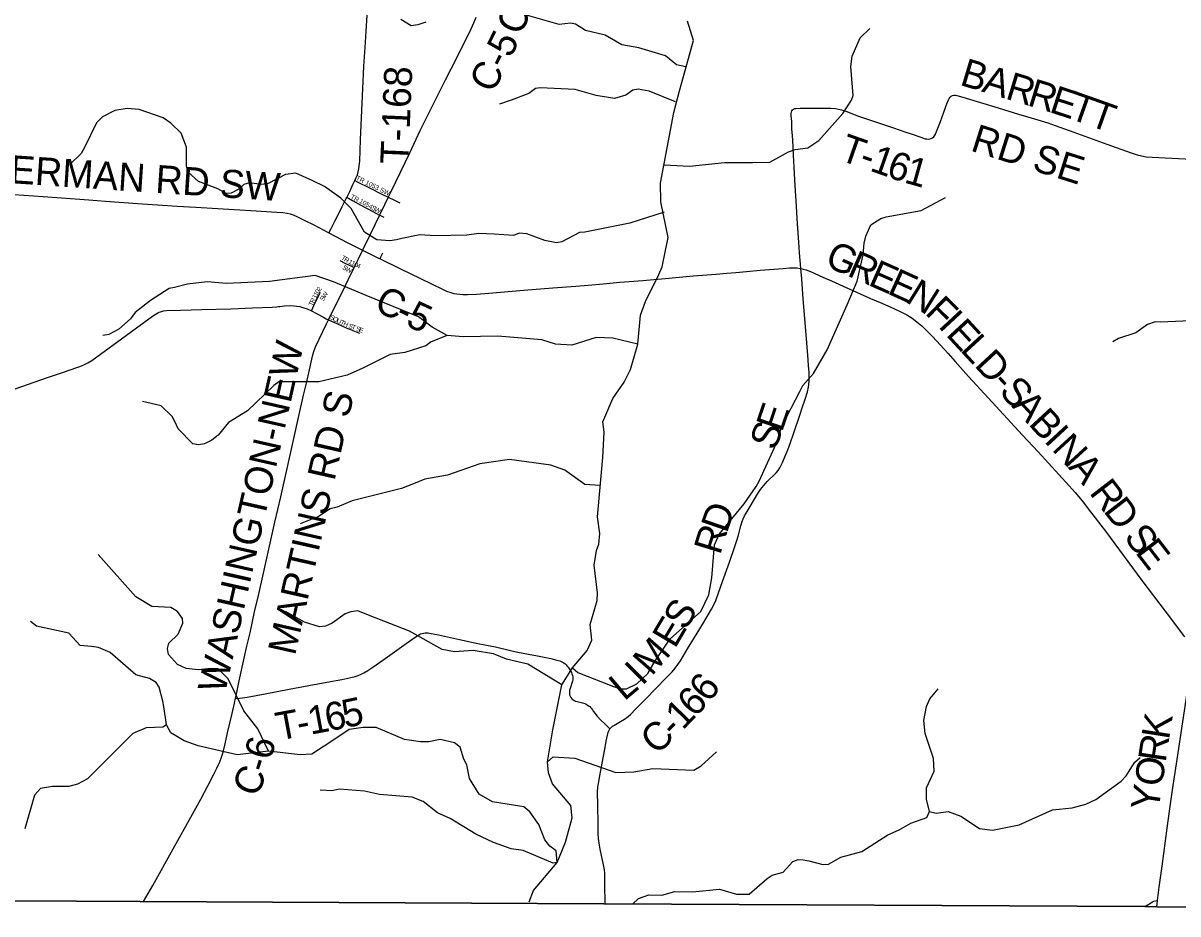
# Model space of a CAD drawing. Extents: x -51392 to 1635000, y 156707 to 696232.
# Drawn here: x 128219 to 140588, y 428826 to 438362 of the extents above; entities that cross this region are included whole.
import ezdxf

# ---------------------------------------------------------------- set-up
doc = ezdxf.new("R2010")
doc.units = 0
for name, color, linetype in [('GM_X_Adjacent_County', 7, 'Continuous'), ('GM_X_County', 7, 'Continuous'), ('GM_X_County_Road', 7, 'Continuous'), ('GM_X_County_Road_Text', 7, 'Continuous'), ('GM_X_Minor_River', 7, 'Continuous'), ('GM_X_Township', 7, 'Continuous'), ('GM_X_Township_Road', 7, 'Continuous'), ('GM_X_Township_Road_Text', 7, 'Continuous'), ('GM_X_Township_Subdivision', 7, 'Continuous'), ('GM_X_Township_Subdivision_Text', 7, 'Continuous')]:
    doc.layers.add(name, color=color, linetype=linetype)

msp = doc.modelspace()

# ---------------------------------------------------------------- linework, layer by layer
at = {"layer": 'GM_X_Adjacent_County'}
msp.add_lwpolyline([(104828, 429256), (108959, 429193), (114698, 429106), (118200, 429053), (121225, 429006), (121630, 429000), (123335, 428991), (129473, 428959), (134438, 428933), (140234, 428904), (140363, 428903), (142841, 428889), (147184, 428866), (150230, 428850), (152105, 428841), (155079, 428826)], dxfattribs=at)
at = {"layer": 'GM_X_County'}
msp.add_lwpolyline([(155079, 428826), (152105, 428841), (150230, 428850), (147184, 428866), (142841, 428889), (140363, 428903), (140234, 428904), (134438, 428933), (129473, 428959), (123335, 428991), (121630, 429000), (121225, 429006), (118200, 429053), (114698, 429106), (108959, 429193), (104828, 429256)], dxfattribs=at)
at = {"layer": 'GM_X_County_Road'}
for points in [[(133068, 438422), (133042, 438360), (133001, 438266), (132799, 437868), (132741, 437751), (132586, 437443), (132469, 437208), (132356, 436971), (132209, 436659), (132152, 436542), (132130, 436499)], [(136548, 435735), (136548, 435739), (136536, 435902), (136528, 436017), (136515, 436213), (136499, 436459), (136488, 436622), (136481, 436754), (136478, 436819), (136471, 436950), (136467, 437031), (136462, 437113), (136456, 437195), (136454, 437228), (136451, 437310), (136447, 437374), (136447, 437393), (136449, 437409), (136454, 437422), (136461, 437433)], [(132130, 436499), (132093, 436424), (132044, 436320), (132037, 436308)], [(132037, 436308), (131987, 436202), (131937, 436099), (131855, 435930)], [(131765, 435746), (131808, 435833), (131851, 435922), (131855, 435930)], [(131855, 435930), (132018, 435851), (132043, 435838)], [(131491, 435186), (131563, 435333), (131628, 435466), (131671, 435554), (131699, 435613), (131765, 435746)], [(132043, 435838), (132253, 435734), (132474, 435627), (132710, 435513), (132755, 435494), (132802, 435478), (132833, 435469), (132865, 435463), (132897, 435459), (132929, 435456), (132978, 435456), (133076, 435462), (133207, 435472), (133583, 435502), (133894, 435527), (134139, 435547), (134270, 435558), (134433, 435573), (134612, 435588), (134710, 435596), (134858, 435608), (135135, 435632), (135396, 435656), (135641, 435675), (135756, 435684), (135854, 435693), (135968, 435704), (136115, 435718), (136360, 435737), (136426, 435741), (136475, 435742), (136508, 435741), (136541, 435737), (136548, 435735)], [(134505, 430808), (134509, 430813), (134520, 430825), (134533, 430835), (134547, 430844), (134618, 430885), (134660, 430911), (134699, 430941), (134724, 430962), (134782, 431020), (134896, 431137), (134988, 431231), (135115, 431359), (135172, 431419), (135204, 431456), (135233, 431496), (135259, 431537), (135336, 431663), (135438, 431832), (135507, 431943), (135558, 432027), (135594, 432088), (135619, 432136), (135638, 432181), (135668, 432264), (135711, 432385), (135784, 432593), (135843, 432761), (135864, 432823), (135877, 432869), (135907, 432979), (135921, 433026), (135933, 433057), (135947, 433087), (135962, 433115), (136005, 433186), (136090, 433328), (136117, 433371), (136152, 433414), (136189, 433454), (136214, 433479), (136250, 433513), (136284, 433548), (136305, 433573), (136323, 433600), (136339, 433629), (136353, 433658), (136379, 433719), (136409, 433795), (136439, 433871), (136472, 433964), (136537, 434167), (136563, 434245), (136594, 434338), (136619, 434416), (136631, 434464), (136636, 434496), (136639, 434529), (136640, 434562), (136637, 434627), (136632, 434693), (136628, 434758), (136612, 434938), (136591, 435199), (136573, 435412), (136558, 435625), (136548, 435735)], [(136548, 435735), (136574, 435730), (136605, 435720), (136651, 435702), (136786, 435641), (136876, 435602), (137041, 435529), (137146, 435482), (137296, 435416), (137416, 435364), (137552, 435305), (137626, 435269), (137684, 435238), (137740, 435203), (137793, 435165), (137844, 435122), (137892, 435077), (137960, 435006), (138126, 434824), (138203, 434739), (138346, 434581), (138557, 434351), (138923, 433953), (139090, 433772), (139201, 433651), (139423, 433410), (139488, 433336), (139561, 433247), (139653, 433131), (139811, 432922), (140203, 432396), (140450, 432068), (140657, 431792)], [(130493, 431133), (130507, 431195), (130535, 431323), (130588, 431563), (130617, 431691), (130650, 431835), (130699, 432060), (130739, 432235), (130786, 432443), (130844, 432699), (130916, 433020), (130978, 433292), (131047, 433596), (131097, 433820), (131148, 434044), (131170, 434140), (131224, 434379), (131253, 434507), (131279, 434619), (131310, 434764), (131322, 434811), (131338, 434858), (131356, 434904), (131390, 434979), (131469, 435142), (131491, 435186)], [(140370, 428969), (140388, 429111), (140418, 429339), (140473, 429745), (140517, 430054), (140538, 430200), (140581, 430479), (140639, 430882), (140687, 431190), (140736, 431547), (140754, 431663)], [(129508, 428960), (129607, 429132), (129825, 429524), (129961, 429767), (130121, 430054), (130199, 430198), (130259, 430315), (130295, 430388), (130326, 430453), (130345, 430504), (130362, 430557), (130385, 430646), (130410, 430763), (130457, 430971), (130482, 431083), (130493, 431133)], [(134453, 428934), (134448, 429148), (134449, 429196), (134448, 429261), (134445, 429297), (134435, 429352), (134400, 429519), (134389, 429584), (134382, 429632), (134380, 429684), (134379, 429786), (134375, 429993), (134372, 430126), (134376, 430185), (134382, 430222), (134396, 430303), (134414, 430400), (134433, 430497), (134453, 430609), (134465, 430674), (134478, 430738), (134486, 430770), (134492, 430785), (134499, 430800), (134505, 430808)], [(140362, 428904), (140366, 428932), (140370, 428969)]]:
    msp.add_lwpolyline(points, dxfattribs=at)
at = {"layer": 'GM_X_Minor_River'}
for points in [[(132533, 438371), (132448, 438344), (132374, 438333), (132264, 438400)], [(135317, 437894), (135218, 437914), (135099, 438013), (134815, 438099), (134633, 438131), (134454, 438233), (134244, 438283), (134135, 438350), (134083, 438362), (133960, 438347), (133611, 438448)], [(133641, 428956), (133684, 429078), (133941, 429378), (134029, 429596), (134100, 429854), (134087, 429985), (133891, 430217), (133846, 430338), (133835, 430454), (133894, 430796), (133990, 431280), (134104, 431462), (134260, 431647), (134311, 431757), (134292, 431925), (134367, 432181), (134373, 432262), (134334, 432559), (134359, 432717), (134384, 432783), (134397, 432899), (134371, 433077), (134428, 433712), (134441, 433983), (134428, 434093), (134536, 434343), (134656, 434518), (134725, 434656), (134805, 434924), (134832, 435235), (134886, 435383), (135028, 435670), (135063, 435754), (135128, 436066), (135049, 436450), (135045, 436650), (135190, 437405), (135250, 437639), (135399, 438177), (135335, 438384)], [(135085, 436844), (135357, 436832), (135732, 436869), (136034, 436870), (136217, 436873), (136418, 436983), (136488, 437009), (136624, 437028), (136741, 437107), (136998, 437393), (137092, 437537), (137108, 437589), (137083, 437898), (137098, 438010), (137186, 438204), (137289, 438303)], [(135207, 437520), (134925, 437635), (134807, 437657), (134751, 437643), (134675, 437591), (134552, 437554), (134358, 437588), (134132, 437650), (133758, 437671), (133706, 437662), (133635, 437610), (133447, 437536), (133320, 437493)], [(135085, 436339), (134719, 436222), (134235, 436126), (134179, 436122), (133988, 436022), (133932, 436010), (133806, 436035), (133614, 436105), (133532, 436112), (133470, 436088), (133264, 436102), (133102, 436111), (132973, 436092), (132631, 436085), (132469, 436097), (132274, 436056), (132218, 436043), (132146, 436031), (132007, 436044), (131874, 436124), (131734, 436379), (131623, 436489), (131448, 436612), (131314, 436676), (131141, 436757), (131030, 436740), (130845, 436644), (130773, 436636), (130645, 436651), (130583, 436636), (130530, 436586), (130448, 436543), (130394, 436537), (130306, 436588), (130096, 436666), (129983, 436769), (129970, 436833), (129969, 437034), (129913, 437185), (129803, 437292), (129718, 437347), (129464, 437439), (129332, 437450), (129202, 437427), (129069, 437358), (129004, 437295), (128876, 437029), (128841, 436967), (128716, 436844)], [(134104, 431462), (134160, 431411), (134543, 431260), (134613, 431237), (134681, 431237), (134793, 431288), (134911, 431399), (134990, 431535), (135148, 431770), (135477, 432064), (135565, 432243), (135595, 432424), (135626, 432778), (135677, 432896), (135942, 433215), (136072, 433402), (136102, 433460), (136284, 433859), (136350, 434053), (136537, 434418), (136570, 434482), (136683, 434612), (136830, 434863), (137046, 435346), (137151, 435600), (137217, 435882), (137228, 436006), (137245, 436082), (137300, 436202), (137407, 436269), (137463, 436289), (137838, 436356), (138100, 436496)], [(134805, 434924), (134536, 434989), (134357, 434996), (134098, 434914), (133922, 434926), (133776, 434973), (133304, 435011), (132932, 435004), (132761, 435018), (132600, 435109), (132453, 435219), (131892, 435446), (131545, 435593), (131349, 435659), (130858, 435597), (130780, 435592), (130399, 435575), (130191, 435593), (129979, 435568), (129840, 435531), (129782, 435520), (129582, 435393), (129421, 435266), (129368, 435195), (129245, 435085), (129137, 435028), (129074, 435019)], [(140806, 435180), (140399, 435161), (140343, 435164), (140263, 435137), (140138, 435045), (139951, 434985), (139889, 434949)], [(132761, 435018), (132591, 434951), (132534, 434907), (132307, 434837), (132151, 434816), (131857, 434670), (131690, 434592), (131387, 434522), (130957, 434522), (130904, 434484), (130623, 434212), (130418, 434087), (130309, 433952), (130242, 433896), (130162, 433859), (130098, 433849), (130036, 433860), (129879, 434020), (129851, 434084), (129816, 434150), (129699, 434266), (129499, 434312)], [(134400, 433414), (134235, 433423), (134020, 433576), (133871, 433631), (133429, 433689), (133110, 433645), (132766, 433522), (132522, 433482), (132399, 433429), (132272, 433382), (131742, 433250), (131584, 433179), (131509, 433164), (131374, 433075), (131310, 433051), (131186, 433002)], [(130846, 430567), (130734, 430809), (130585, 431001), (130416, 431343), (130309, 431450), (130235, 431453), (130094, 431438), (129966, 431453), (129873, 431496), (129775, 431605), (129766, 431669), (129780, 431725), (129881, 431822), (129929, 431938), (129925, 431989), (129872, 432065), (129800, 432108), (129598, 432118), (129426, 432221), (129022, 432672)], [(133990, 431280), (133624, 431500), (133398, 431554), (133258, 431609), (133038, 431647), (132840, 431633), (132706, 431658), (132359, 431852), (131938, 432016), (131806, 432069), (131728, 432061), (131670, 432038), (131531, 431939), (131458, 431905), (131392, 431898), (131234, 431951), (131029, 432065)], [(133941, 429378), (133929, 429501), (133861, 429550), (133807, 429618), (133743, 429783), (133646, 429920), (133584, 429973), (133246, 430026), (133103, 430107), (133000, 430275), (132973, 430423), (132938, 430484), (132899, 430612), (132841, 430657), (132687, 430692), (132565, 430669), (132477, 430668), (132303, 430695), (131999, 430820), (131861, 430823), (131713, 430801), (131515, 430668), (131310, 430535), (131186, 430530), (130846, 430567), (130511, 430530), (130093, 430626), (129945, 430679), (129800, 430765), (129755, 430851), (129726, 431048), (129715, 431102), (129676, 431253), (129643, 431305), (129573, 431348), (129427, 431385), (129151, 431626), (129025, 431679), (128953, 431688), (128831, 431701), (128710, 431830), (128364, 431908), (128300, 431956)], [(134747, 428929), (134809, 428992), (134922, 429031), (135062, 429028), (135198, 429067), (135387, 429062), (135677, 429091), (135859, 429039), (135997, 429036), (136187, 429207), (136243, 429241), (136360, 429274), (136463, 429387), (136519, 429409), (136573, 429406), (136633, 429396), (136783, 429354), (136845, 429360), (136976, 429433), (137201, 429495), (137481, 429673), (137602, 429728), (137726, 429797), (137899, 429860), (137926, 429924), (137895, 430053), (137894, 430177), (137978, 430353), (137971, 430489), (137879, 430758), (137868, 430895), (137894, 431047), (137930, 431127), (138019, 431234)], [(129755, 430851), (129714, 430826), (129536, 430817), (129395, 430756), (128909, 430273), (128800, 430214), (128708, 430191), (128535, 430190), (128407, 430167), (128342, 430097), (128239, 429738)], [(133835, 430454), (133895, 430507), (134128, 430493), (134569, 430341), (134761, 430346), (134964, 430382), (135404, 430366), (135483, 430410), (135646, 430563)], [(137926, 429924), (137998, 429905), (138128, 429922), (138264, 429873), (138463, 429739), (138603, 429724), (138888, 429780), (139244, 429941), (139456, 429961), (139601, 430002), (139708, 430051), (139980, 430247), (140034, 430303), (140126, 430451), (140182, 430502)], [(133941, 429378), (133897, 429369), (133574, 429504), (133448, 429523), (133258, 429589), (133069, 429681), (132794, 429849), (132658, 429909), (132505, 430030), (132385, 430077), (132037, 430104), (131877, 430140), (131609, 430160), (131525, 430145), (131401, 430150)]]:
    msp.add_lwpolyline(points, dxfattribs=at)
at = {"layer": 'GM_X_Township'}
msp.add_lwpolyline([(155079, 428826), (152105, 428841), (150230, 428850), (147184, 428866), (142841, 428889), (140363, 428903), (140234, 428904), (134438, 428933), (129473, 428959), (123335, 428991)], dxfattribs=at)
at = {"layer": 'GM_X_Township_Road'}
for points in [[(131772, 436676), (131787, 436708), (131799, 436738), (131808, 436770), (131816, 436802), (131820, 436834), (131824, 436883), (131833, 437114), (131844, 437352), (131857, 437660), (131869, 437902), (131882, 438100), (131894, 438274), (131909, 438504), (131922, 438673), (131932, 438821), (131946, 438948)], [(136461, 437433), (136469, 437440), (136478, 437444), (136485, 437447), (136495, 437450), (136542, 437452), (136657, 437453), (136772, 437453), (136870, 437451), (136919, 437447), (136951, 437442), (136983, 437434), (137030, 437418), (137168, 437367), (137338, 437308), (137540, 437240), (137664, 437199), (137742, 437173), (137835, 437141), (137882, 437125), (137898, 437122), (137914, 437121), (137930, 437122), (137945, 437126), (137959, 437134), (137972, 437145), (137982, 437157), (137990, 437172), (138003, 437202), (138044, 437309), (138118, 437509), (138131, 437540), (138138, 437554), (138148, 437568), (138159, 437579), (138173, 437586), (138189, 437590), (138205, 437590), (138221, 437587), (138284, 437568), (138661, 437455), (138880, 437388), (139053, 437337), (139194, 437294), (139272, 437267), (139472, 437196), (139827, 437068), (140088, 436972), (140150, 436951), (140198, 436940), (140247, 436932), (140312, 436926), (140803, 436902)], [(131686, 436497), (131717, 436559), (131752, 436633), (131772, 436676)], [(127614, 436565), (127828, 436550), (128122, 436529), (128433, 436507), (128923, 436470), (129103, 436457), (129446, 436432), (129659, 436417), (129871, 436404), (130068, 436392), (130362, 436375), (130542, 436363), (130657, 436357), (130935, 436340), (131000, 436335), (131049, 436327), (131080, 436320), (131112, 436309), (131157, 436290), (131231, 436254), (131333, 436202), (131494, 436117)], [(131494, 436117), (131517, 436164), (131563, 436251), (131593, 436309), (131636, 436398), (131680, 436486), (131686, 436497)], [(131494, 436117), (131691, 436013), (131806, 435955), (131855, 435930)], [(128063, 434424), (128482, 434568), (128653, 434626), (128793, 434674), (128839, 434691), (128884, 434711), (128913, 434726), (128955, 434752), (129049, 434818), (129274, 434983), (129433, 435099), (129513, 435156), (129526, 435167), (129553, 435186), (129605, 435225), (129633, 435244), (129662, 435261), (129677, 435267), (129692, 435273), (129723, 435282), (129756, 435285), (129904, 435289), (130133, 435295), (130445, 435305), (130675, 435313), (130888, 435322), (130937, 435326), (130954, 435327), (130970, 435330), (131020, 435335), (131085, 435338), (131118, 435337), (131150, 435334), (131182, 435328), (131214, 435319), (131260, 435302), (131307, 435282)], [(131307, 435282), (131363, 435252), (131436, 435213), (131465, 435198), (131491, 435186)], [(130493, 431133), (130536, 431136), (130569, 431139), (130618, 431146), (130715, 431164), (130811, 431182), (131069, 431231), (131279, 431270), (131472, 431307), (131633, 431337), (131730, 431357), (131777, 431369), (131808, 431380), (131839, 431392), (131868, 431407), (131910, 431432), (131965, 431469), (132072, 431544), (132272, 431687), (132407, 431781), (132448, 431808), (132477, 431824), (132492, 431829), (132508, 431833), (132524, 431835), (132540, 431836), (132557, 431835), (132589, 431829), (132669, 431812), (132893, 431763), (133070, 431726), (133183, 431704), (133279, 431685), (133439, 431647), (133519, 431629), (133631, 431608), (133728, 431589), (133872, 431559), (133936, 431544), (133968, 431535), (133983, 431528), (133998, 431521), (134012, 431513), (134025, 431503), (134037, 431492), (134048, 431480), (134058, 431467), (134076, 431440), (134092, 431411), (134098, 431396), (134104, 431380), (134107, 431364), (134108, 431348), (134106, 431332), (134102, 431316), (134077, 431238), (134073, 431222), (134071, 431205), (134071, 431189), (134073, 431173), (134078, 431157), (134086, 431143), (134096, 431130), (134108, 431120), (134121, 431110), (134136, 431103), (134155, 431100), (134210, 431087), (134234, 431079), (134250, 431071), (134262, 431065), (134276, 431055), (134289, 431045), (134299, 431034), (134307, 431024), (134316, 431012), (134326, 430997), (134345, 430971), (134363, 430945), (134410, 430897), (134446, 430864), (134482, 430830), (134505, 430808)], [(140234, 428904), (140275, 428932), (140314, 428955), (140330, 428961), (140349, 428966), (140370, 428969)]]:
    msp.add_lwpolyline(points, dxfattribs=at)
at = {"layer": 'GM_X_Township_Subdivision'}
for points in [[(131772, 436676), (131797, 436664), (131930, 436598), (132062, 436531), (132130, 436499)], [(131686, 436497), (131704, 436487), (131747, 436462), (131835, 436415), (131966, 436345), (132037, 436308)], [(132130, 436499), (132196, 436467), (132255, 436438)], [(132037, 436308), (132039, 436307), (132084, 436286)], [(132043, 435838), (132052, 435859), (132073, 435902)], [(131613, 435822), (131673, 435790), (131735, 435760), (131765, 435746)], [(131307, 435282), (131323, 435314), (131344, 435363), (131389, 435452), (131404, 435481)], [(131491, 435186), (131579, 435147), (131681, 435101), (131770, 435064), (131822, 435044)]]:
    msp.add_lwpolyline(points, dxfattribs=at)

# ---------------------------------------------------------------- texts
at = {"layer": 'GM_X_County_Road_Text'}
for s, rotation, p in [('C-6', 65.7698, (133547, 438218)), ('C-5', 63.5662, (133253, 437601)), ('G', 336.1407, (136793, 435769)), ('R', 336.1438, (137034, 435663)), ('E', 336.1148, (137259, 435563)), ('E', 335.4725, (137464, 435472)), ('C', 333.401, (131964, 435298)), ('N', 328.0246, (137659, 435384)), ('5', 335.1357, (132304, 435130)), ('F', 315.3857, (137869, 435255)), ('-', 334.2137, (132189, 435186)), ('I', 312.8275, (138011, 435116)), ('E', 312.7237, (138094, 435025)), ('L', 312.7191, (138247, 434860)), ('WASHINGTON-NEW', 77.2562, (130380, 431176)), ('D', 312.7191, (138399, 434696)), ('-', 312.7215, (138578, 434502)), ('S', 312.7186, (138662, 434411)), ('MARTINS RD S', 77.2647, (131131, 431583)), ('E', 71.202, (136347, 433975)), ('A', 312.7191, (138799, 434262)), ('B', 312.7193, (138978, 434068)), ('S', 69.7342, (136274, 433777)), ('I', 312.7215, (139145, 433887)), ('N', 312.517, (139229, 433797)), ('A', 310.4512, (139405, 433605)), ('R', 307.6969, (139631, 433334)), ('D', 307.6081, (139782, 433140)), ('D', 70.9856, (135756, 432893)), ('R', 72.8435, (135684, 432660)), ('S', 307.6094, (140000, 432857)), ('E', 307.6086, (140123, 432697)), ('S', 58.6291, (135314, 431851)), ('E', 59.3251, (135200, 431658)), ('M', 48.9965, (134952, 431365)), ('I', 44.8698, (134848, 431261)), ('L', 40.1608, (134657, 431098)), ('6', 51.9649, (135564, 431079)), ('6', 46.0095, (135413, 430921)), ('1', 45.8274, (135284, 430787)), ('K', 81.0385, (140492, 430684)), ('C', 42.2858, (135001, 430519)), ('-', 45.9395, (135198, 430699)), ('6', 76.4342, (130877, 430464)), ('R', 81.5719, (140456, 430441)), ('-', 72.9804, (130836, 430327)), ('O', 81.5807, (140417, 430180)), ('C', 65.2452, (130717, 430062)), ('Y', 81.5811, (140378, 429919))]:
    msp.add_text(s, height=300, rotation=rotation, dxfattribs=at).set_placement(p)
at = {"layer": 'GM_X_Township_Road_Text'}
for s, rotation, p in [('B', 343.249, (138241, 437703)), ('T-168', 87.4895, (132343, 436848)), ('A', 343.2475, (138477, 437632)), ('R', 343.2496, (138729, 437556)), ('R', 343.0404, (138965, 437485)), ('E', 341.8312, (139199, 437414)), ('T', 340.5964, (139411, 437344)), ('T', 340.3306, (139622, 437270)), ('RD SE', 342.479, (138356, 437000)), ('T', 340.6411, (136948, 436900)), ('ZIMMERMAN RD SW', 356.1827, (127050, 436718)), ('1', 340.7562, (137277, 436785)), ('6', 341.1281, (137453, 436723)), ('-', 340.6776, (137160, 436825)), ('1', 344.1716, (137645, 436658)), ('1', 10.6105, (131297, 430744)), ('6', 10.8559, (131480, 430779)), ('5', 11.8776, (131667, 430815)), ('T', 10.5272, (130955, 430681)), ('-', 10.5428, (131176, 430722))]:
    msp.add_text(s, height=300, rotation=rotation, dxfattribs=at).set_placement(p)
at = {"layer": 'GM_X_Township_Subdivision_Text'}
for s, rotation, p in [('TR 1053 SW', 333.6208, (131780, 436688)), ('TR', 331.1821, (131721, 436489)), ('1054', 331.2913, (131814, 436442)), ('S', 328.8111, (131943, 436372)), ('W', 333.5703, (131977, 436351)), ('T', 329.9497, (131622, 435837)), ('S', 327.9248, (131634, 435734)), ('R', 329.9498, (131652, 435819)), ('W', 333.6433, (131668, 435712)), ('1', 329.9495, (131698, 435793)), ('1', 333.2547, (131727, 435776)), ('0', 336.2385, (131758, 435761)), ('4', 336.605, (131786, 435748)), ('0', 56.58, (131383, 435461)), ('2', 55.1424, (131400, 435487)), ('T', 64.6699, (131319, 435328)), ('R', 64.6816, (131334, 435360)), ('1', 64.6858, (131356, 435408)), ('1', 61.487, (131369, 435435)), ('S', 61.7493, (131439, 435383)), ('W', 57.1235, (131455, 435413)), ('S', 332.8004, (131500, 435198)), ('O', 332.8756, (131531, 435182)), ('U', 334.195, (131571, 435161)), ('T', 334.9966, (131612, 435142)), ('H', 335.5432, (131644, 435127)), ('S', 338.5057, (131699, 435102)), ('T', 339.0487, (131732, 435089)), ('S', 340.8907, (131779, 435072)), ('E', 341.2522, (131813, 435060))]:
    msp.add_text(s, height=50, rotation=rotation, dxfattribs=at).set_placement(p)

doc.saveas('drawing.dxf')
